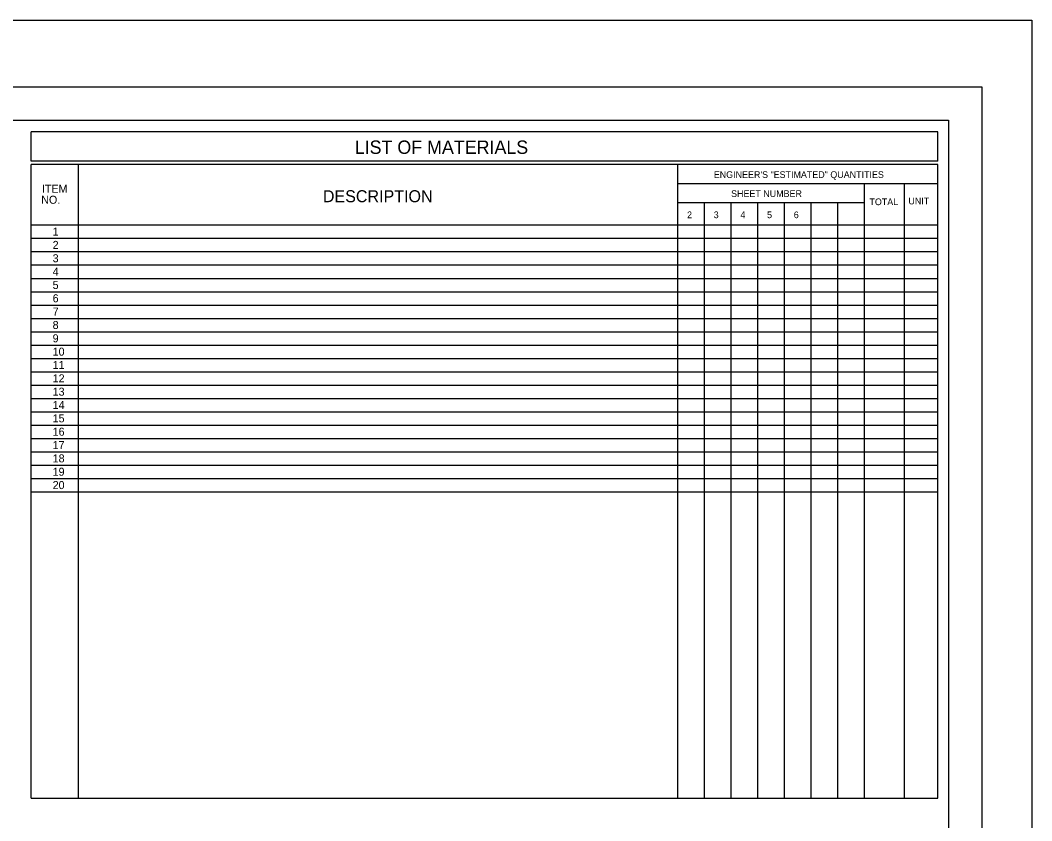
# Model space of a CAD drawing. Extents: x 837 to 1117, y 1316 to 1424.
# Drawn here: x 862.6 to 877.77, y 1410.24 to 1422.24 of the extents above; entities that cross this region are included whole.
import ezdxf

# ---------------------------------------------------------------- set-up
doc = ezdxf.new("R2010")
doc.units = 0
for name, color, linetype in [('0 (Construction)', 7, 'Continuous'), ('BASEMAP', 7, 'Continuous'), ('LLINES', 7, 'Continuous')]:
    doc.layers.add(name, color=color, linetype=linetype)

msp = doc.modelspace()

# ---------------------------------------------------------------- linework, layer by layer
at = {"layer": '0 (Construction)'}
msp.add_lwpolyline([(841.77, 1422.24), (877.77, 1422.24), (877.77, 1398.24), (841.77, 1398.24)], close=True, dxfattribs=at)
at = {"layer": 'BASEMAP'}
for p, q in [((843.02, 1421.24), (877.02, 1421.24)), ((877.02, 1421.24), (877.02, 1399.24)), ((843.52, 1420.74), (876.52, 1420.74)), ((876.52, 1420.74), (876.52, 1399.74)), ((876.362, 1420.569), (862.767, 1420.569)), ((862.767, 1420.126), (862.767, 1420.569)), ((876.362, 1420.126), (876.362, 1420.569)), ((876.362, 1420.126), (862.767, 1420.126)), ((862.767, 1410.581), (862.767, 1420.078)), ((876.362, 1420.078), (862.767, 1420.078)), ((863.477, 1410.581), (863.477, 1420.078)), ((872.462, 1410.581), (872.462, 1420.078)), ((876.362, 1410.581), (876.362, 1420.078)), ((876.362, 1419.79), (872.462, 1419.79)), ((875.262, 1410.581), (875.262, 1419.79)), ((875.862, 1410.581), (875.862, 1419.79)), ((875.262, 1419.502), (872.462, 1419.502)), ((872.862, 1410.581), (872.862, 1419.502)), ((873.262, 1410.581), (873.262, 1419.502)), ((873.662, 1410.581), (873.662, 1419.502)), ((874.062, 1410.581), (874.062, 1419.502)), ((874.462, 1410.581), (874.462, 1419.502)), ((874.862, 1410.581), (874.862, 1419.502)), ((876.362, 1419.166), (862.767, 1419.166)), ((876.362, 1418.966), (862.767, 1418.966)), ((876.362, 1418.766), (862.767, 1418.766)), ((876.362, 1418.566), (862.767, 1418.566)), ((876.362, 1418.366), (862.767, 1418.366)), ((876.362, 1418.166), (862.767, 1418.166)), ((876.362, 1417.966), (862.767, 1417.966)), ((876.362, 1417.766), (862.767, 1417.766)), ((876.362, 1417.566), (862.767, 1417.566)), ((876.362, 1417.366), (862.767, 1417.366)), ((876.362, 1417.166), (862.767, 1417.166)), ((876.362, 1416.966), (862.767, 1416.966)), ((876.362, 1416.766), (862.767, 1416.766)), ((876.362, 1416.566), (862.767, 1416.566)), ((876.362, 1416.366), (862.767, 1416.366)), ((876.362, 1416.166), (862.767, 1416.166)), ((876.362, 1415.966), (862.767, 1415.966)), ((876.362, 1415.766), (862.767, 1415.766)), ((876.362, 1415.566), (862.767, 1415.566)), ((876.362, 1415.366), (862.767, 1415.366)), ((876.362, 1415.166), (862.767, 1415.166)), ((862.767, 1410.581), (876.362, 1410.581))]:
    msp.add_line(p, q, dxfattribs=at)

# ---------------------------------------------------------------- texts
at = {"layer": 'LLINES'}
for s, height, p in [('LIST OF MATERIALS', 0.2, (867.618, 1420.237)), ('ENGINEER\'S "ESTIMATED" QUANTITIES', 0.1, (873.002, 1419.876)), ('ITEM', 0.12, (862.927, 1419.654)), (' NO.', 0.12, (862.872, 1419.489)), ('DESCRIPTION', 0.18, (867.14, 1419.512)), ('SHEET NUMBER', 0.1, (873.261, 1419.591)), ('TOTAL', 0.1, (875.336, 1419.468)), ('UNIT', 0.1, (875.92, 1419.48)), ('2', 0.1, (872.601, 1419.273)), ('3', 0.1, (873.001, 1419.273)), ('4', 0.1, (873.401, 1419.273)), ('5', 0.1, (873.801, 1419.273)), ('6', 0.1, (874.201, 1419.273)), ('1', 0.12, (863.088, 1419.012)), ('2', 0.12, (863.088, 1418.812)), ('3', 0.12, (863.088, 1418.612)), ('4', 0.12, (863.088, 1418.412)), ('5', 0.12, (863.088, 1418.212)), ('6', 0.12, (863.088, 1418.012)), ('7', 0.12, (863.088, 1417.812)), ('8', 0.12, (863.088, 1417.612)), ('9', 0.12, (863.088, 1417.412)), ('10', 0.12, (863.088, 1417.212)), ('11', 0.12, (863.088, 1417.012)), ('12', 0.12, (863.088, 1416.812)), ('13', 0.12, (863.088, 1416.612)), ('14', 0.12, (863.088, 1416.412)), ('15', 0.12, (863.088, 1416.212)), ('16', 0.12, (863.088, 1416.012)), ('17', 0.12, (863.088, 1415.812)), ('18', 0.12, (863.088, 1415.612)), ('19', 0.12, (863.088, 1415.412)), ('20', 0.12, (863.088, 1415.212))]:
    msp.add_text(s, height=height, dxfattribs=at).set_placement(p)

doc.saveas('drawing.dxf')
